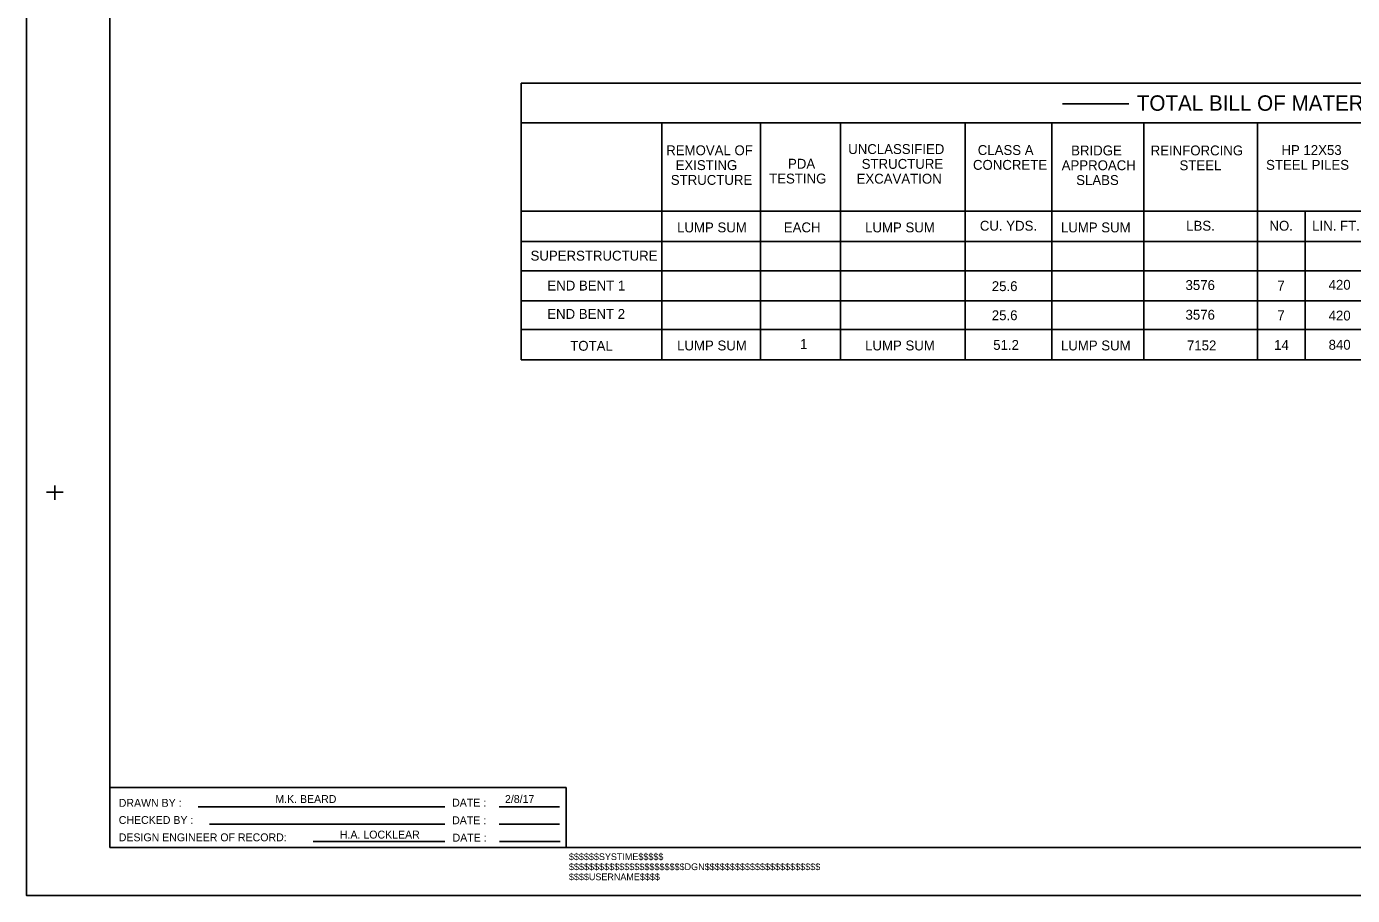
# Model space of a CAD drawing. Extents: x 985 to 1514, y -701 to -21.
# Drawn here: x 985.2 to 1253.7, y -701.2 to -525.2 of the extents above; entities that cross this region are included whole.
import ezdxf

# ---------------------------------------------------------------- set-up
doc = ezdxf.new("R2010")
doc.units = 0
for name, color, linetype in [('Default', 7, 'Continuous'), ('Plan Sheet CELL', 7, 'Continuous'), ('Plot Label CELL', 7, 'Continuous'), ('Plot Shape CELL', 7, 'Continuous'), ('Subtitle Text', 7, 'Continuous'), ('Text', 7, 'Continuous'), ('Typical Text General CELL', 7, 'Continuous')]:
    doc.layers.add(name, color=color, linetype=linetype)

msp = doc.modelspace()

# ---------------------------------------------------------------- linework, layer by layer
at = {"layer": 'Default'}
for p, q in [((1085.36, -536.66), (1085.36, -592.68)), ((1391.43, -536.66), (1085.36, -536.66)), ((1301.25, -536.66), (1229.53, -536.66)), ((1208.42, -540.84), (1195.02, -540.84)), ((1310.78, -544.65), (1085.36, -544.65)), ((1175.28, -544.72), (1175.28, -544.72)), ((1175.28, -544.72), (1175.28, -544.72)), ((1374.09, -544.65), (1233.81, -544.65)), ((1085.36, -562.58), (1310.78, -562.58)), ((1085.36, -563.2), (1085.36, -563.2)), ((1133.88, -562.57), (1205.75, -562.57)), ((1175.28, -562.58), (1391.43, -562.58)), ((1085.36, -592.68), (1391.43, -592.68)), ((1175.28, -592.74), (1175.28, -592.74)), ((1175.28, -592.74), (1175.28, -592.74))]:
    msp.add_line(p, q, dxfattribs=at)
at = {"layer": 'Plan Sheet CELL'}
for p, q in [((1002.1, -691.46), (1002.1, -355.46)), ((989.31, -619.46), (992.67, -619.46)), ((990.95, -621.04), (990.95, -618.14)), ((1002.1, -679.27), (1094.48, -679.27)), ((1094.48, -679.27), (1094.48, -691.46)), ((1019.99, -683.23), (1069.94, -683.23)), ((1080.94, -683.23), (1093.17, -683.23)), ((1022.28, -686.74), (1069.94, -686.74)), ((1080.94, -686.74), (1093.17, -686.74)), ((1002.1, -691.46), (1514.1, -691.46)), ((1043.25, -690.25), (1069.94, -690.25)), ((1043.25, -690.25), (1069.94, -690.25)), ((1081.02, -690.25), (1093.26, -690.25)), ((1081.02, -690.25), (1093.26, -690.25)), ((985.23, -701.16), (985.23, -701.16))]:
    msp.add_line(p, q, dxfattribs=at)
at = {"layer": 'Plot Shape CELL'}
msp.add_lwpolyline([(985.23, -349.16), (1514.24, -349.16), (1514.24, -701.16), (985.23, -701.16)], close=True, dxfattribs=at)
at = {"layer": 'Typical Text General CELL'}
for p, q in [((1113.89, -544.65), (1113.89, -592.68)), ((1113.89, -544.65), (1113.89, -592.68)), ((1133.88, -544.65), (1133.88, -592.68)), ((1133.88, -544.65), (1133.88, -592.68)), ((1150.07, -544.65), (1150.07, -592.68)), ((1175.28, -592.68), (1175.28, -544.65)), ((1192.84, -544.65), (1192.84, -592.68)), ((1211.49, -544.65), (1211.49, -592.68)), ((1234.5, -544.65), (1234.5, -592.68)), ((1234.5, -544.65), (1234.5, -592.68)), ((1244.13, -562.58), (1244.13, -592.68)), ((1085.36, -568.7), (1310.78, -568.7)), ((1175.28, -568.7), (1391.43, -568.7)), ((1085.36, -574.63), (1310.78, -574.63)), ((1175.28, -574.63), (1391.43, -574.63)), ((1085.36, -580.69), (1391.43, -580.69)), ((1085.36, -586.49), (1310.78, -586.49)), ((1175.28, -586.49), (1391.43, -586.49))]:
    msp.add_line(p, q, dxfattribs=at)

# ---------------------------------------------------------------- texts
at = {"layer": 'Default'}
for s, height, p in [('TOTAL BILL OF MATERIAL', 3.1223, (1210.04, -542.22)), ('REMOVAL OF', 2, (1114.76, -551.23)), ('UNCLASSIFIED', 2, (1151.61, -550.98)), ('CLASS A', 2, (1177.84, -551.18)), ('BRIDGE', 2, (1196.75, -551.26)), ('REINFORCING', 2, (1212.85, -551.26)), ('HP 12X53', 2, (1239.33, -551.18)), ('EXISTING', 2, (1116.66, -554.23)), ('PDA', 2, (1139.42, -553.95)), ('STRUCTURE', 2, (1154.34, -553.98)), ('CONCRETE', 2, (1176.87, -554.18)), ('APPROACH', 2, (1194.83, -554.26)), ('STEEL', 2, (1218.69, -554.26)), ('STEEL PILES', 2, (1236.22, -554.18)), ('STRUCTURE ', 2, (1115.69, -557.23)), ('TESTING', 2, (1135.6, -556.95)), ('EXCAVATION', 2, (1153.3, -556.98)), ('SLABS', 2, (1197.77, -557.26)), ('LUMP SUM', 2, (1116.96, -566.85)), ('EACH', 2, (1138.57, -566.84)), ('LUMP SUM', 2, (1155.03, -566.85)), ('CU. YDS.', 2, (1178.26, -566.51)), ('LUMP SUM', 2, (1194.68, -566.85)), ('LBS.', 2, (1220.04, -566.51)), ('NO.', 2, (1236.9, -566.51)), ('LIN. FT.', 2, (1245.55, -566.51)), ('LUMP SUM', 2, (1116.96, -590.76)), ('LUMP SUM', 2, (1155.03, -590.76)), ('LUMP SUM', 2, (1194.68, -590.76))]:
    msp.add_text(s, height=height, dxfattribs=at).set_placement(p)
at = {"layer": 'Plan Sheet CELL'}
for s, height, p in [('DRAWN BY :', 1.6, (1003.91, -683.2)), ('DATE :', 1.6, (1071.41, -683.15)), ('CHECKED BY :', 1.5999, (1003.91, -686.67)), ('DATE :', 1.6, (1071.41, -686.73)), ('DESIGN ENGINEER OF RECORD:', 1.5999, (1003.91, -690.18)), ('DATE :', 1.6, (1071.5, -690.24))]:
    msp.add_text(s, height=height, dxfattribs=at).set_placement(p)
at = {"layer": 'Plot Label CELL'}
for s, height, p in [('$$$$$$SYSTIME$$$$$', 1.3606, (1095.06, -693.98)), ('$$$$$$$$$$$$$$$$$$$$$$$DGN$$$$$$$$$$$$$$$$$$$$$$$', 1.3689, (1095.06, -696.02)), ('$$$$USERNAME$$$$', 1.3606, (1095.06, -698.06))]:
    msp.add_text(s, height=height, dxfattribs=at).set_placement(p)
at = {"layer": 'Subtitle Text'}
for s, height, p in [('M.K. BEARD', 1.6, (1035.61, -682.42)), ('2/8/17', 1.6, (1082.11, -682.42)), ('H.A. LOCKLEAR', 1.5999, (1048.68, -689.62))]:
    msp.add_text(s, height=height, dxfattribs=at).set_placement(p)
at = {"layer": 'Text'}
for s, p in [('25.6', (1180.68, -578.75)), ('3576', (1219.91, -578.53)), ('7', (1238.51, -578.64)), ('420', (1248.88, -578.47)), ('3576', (1219.91, -584.54)), ('25.6', (1180.68, -584.64)), ('7', (1238.51, -584.64)), ('420', (1248.88, -584.7)), ('1', (1141.85, -590.47)), ('51.2', (1180.97, -590.65)), ('7152', (1220.2, -590.75)), ('14', (1237.85, -590.65)), ('840', (1248.88, -590.62))]:
    msp.add_text(s, height=2, dxfattribs=at).set_placement(p)
at = {"layer": 'Typical Text General CELL'}
for s, p in [('SUPERSTRUCTURE', (1087.29, -572.57)), ('END BENT 1', (1090.7, -578.63)), ('END BENT 2', (1090.67, -584.37)), ('TOTAL', (1095.32, -590.83))]:
    msp.add_text(s, height=2, dxfattribs=at).set_placement(p)

doc.saveas('drawing.dxf')
